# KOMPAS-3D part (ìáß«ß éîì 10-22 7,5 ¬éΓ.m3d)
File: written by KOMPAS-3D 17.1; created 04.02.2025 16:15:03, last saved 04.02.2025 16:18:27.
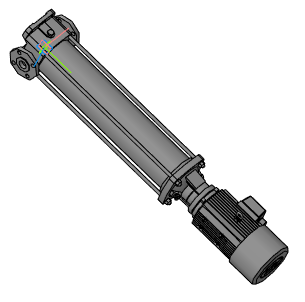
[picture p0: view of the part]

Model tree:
1. Операция без истории:1  (labels: Насос ВМН 10-22 7,5 кВт)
